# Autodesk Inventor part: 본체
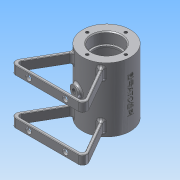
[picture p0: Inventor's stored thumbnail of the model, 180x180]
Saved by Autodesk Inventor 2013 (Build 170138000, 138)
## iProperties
Created: 2016-03
Part Number: 본체
Material: 알루미늄 6061
Document SubType Name: Modeling
Designer: Administrator
Density: 2.71 g/cm^3
Mass: 213.519 g
Surface Area: 333.696 cm^2
Volume: 78.7893 cm^3
Author: Administrator
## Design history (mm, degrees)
sketch "스케치1"
  geometry: C1 r 26 at (0, 0); 1 further point
  constraints: 1 centre point, 1 coincident
  dimensions: "d0" = 52 diameter of C1
extrude "돌출1" new body sketch "스케치1" distance "d1" = 35; taper "d2" = 0 deg
node "작업 평면1"
sketch "스케치2"
  geometry: L1 (0, 0)-(0, -65); L2 (-42.594, -65)-(42.594, -65); L3 (0, 8.775)-(-42.594, -65); L4 (42.594, -65)-(0, 8.775); 2 further points
  constraints: 8 end point, 1 midpoint, 1 perpendicular, 1 point on line, 1 vertical, 2 other
  dimensions: "d4" = 65 distance of L1.end L1.start; "d5" = 30 deg angle of L1 L3; "d7" = 30 deg angle of L4 L1 (derived); "d9" = 85.18802 distance of L2.start L2.end; "d10" = 73.77499 vertical distance of L2.end L3.start; "d97" = 45 distance from line of L2 point (16.613, -20) (derived)
feature "리브1" sketch "스케치2" dims "d11" = 3, "d12" = 10, "d13" = 0, "d14" = 0, "d15" = 1, "d16" = 1
hole "구멍1" diameter "d19" = 28; stored, may be unused: countersink angle "d23" = 90 deg, drill point angle "d25" = 0 deg; dims "d17" = 10, "d18" = 10, "d20" = 6, "d21" = 32, "d22" = 12, "d24" = 14
hole "구멍2" diameter "d28" = 42; stored, may be unused: countersink angle "d32" = 90 deg, drill point angle "d34" = 0 deg; dims "d26" = 10, "d27" = 10, "d29" = 6, "d30" = 32, "d31" = 12, "d33" = 21
sketch "스케치3"
  geometry: C1 r 16 at (0, 0) reference; 1 further point
  constraints: 1 vertical alignment
  dimensions: "d35" = 21 distance of C1.centre point (0, 21)
hole "구멍3" sketch "스케치3" at (0, 21) diameter "d36" = 3.242; stored, may be unused: countersink angle "d40" = 90 deg, drill point angle "d42" = 118 deg; dims "d37" = 8, "d38" = 32, "d39" = 12, "d41" = 10
fillet "모깎기1" dims "d46" = 0.3
fillet "모깎기2" dims "d47" = 3
fillet "모깎기3" dims "d48" = 5
fillet "모깎기4" dims "d49" = 3
fillet "모깎기5" dims "d50" = 0.5
fillet "모깎기6" dims "d51" = 3
node "작업 평면2"
sketch "스케치4"
  geometry: C1 r 5 at (0, 0); 1 further point
  constraints: 1 centre point, 1 coincident
  dimensions: "d53" = 10 diameter of C1
extrude "돌출2" join sketch "스케치4" stored distance "d54" = 35; taper "d55" = 0 deg
hole "구멍4" diameter "d58" = 5.188; stored, may be unused: countersink angle "d62" = 90 deg, drill point angle "d64" = 118 deg; dims "d56" = 10, "d57" = 10, "d59" = 8, "d60" = 32, "d61" = 12, "d63" = 10
sketch "스케치5"
  geometry: L1 (-5, 25.515)-(-5, 29) reference; L2 (-5, 29)-(-2.594, 29) reference; L3 (-2.594, 29)-(-2.594, 20.839) reference; L4 (2.594, 20.839)-(2.594, 29) reference; L5 (2.594, 29)-(5, 29) reference; L6 (5, 29)-(5, 25.515) reference; L7 (0, 0)-(-7.506, -28.012); L8 (0, 0)-(29, 0); A1 r 21 centre (0, 0) between (-2.594, 20.839) and (2.594, 20.839) reference; A2 r 26 centre (0, 0) between (-5, 25.515) and (5, 25.515) reference; 1 further point
  constraints: 4 end point, 1 equal length, 1 horizontal
  dimensions: "d66" = 29 distance of L7.start L7.end; "d67" = 105 deg angle of L7 L8
  node "절단 모서리 투영1"
node "작업 평면3"
sketch "스케치6"
  geometry: C1 r 6 at (0, 0); 1 further point
  constraints: 1 centre point, 1 coincident
  dimensions: "d68" = 12 diameter of C1
extrude "돌출3" join sketch "스케치6" stored distance "d69" = 35; taper "d70" = 0 deg
sketch "스케치7"
  geometry: C1 r 6 at (0, 0) reference; 1 further point
  constraints: 1 coincident
hole "구멍5" sketch "스케치7" at (0, 0) diameter "d71" = 5.188; stored, may be unused: countersink angle "d75" = 90 deg, drill point angle "d77" = 118 deg; dims "d72" = 8, "d73" = 32, "d74" = 12, "d76" = 10
fillet "모깎기8" dims "d78" = 2
node "작업 평면4"
sketch "스케치8"
  geometry: L1 (-65, -29.5)-(-65, -20.5) reference; 2 further points
  constraints: 1 coincident, 1 other
  dimensions: "d79" = 65 distance from line of point (0, 0) L1 (derived)
feature "엠보싱1" sketch "스케치8" dims "d1" = 35, "d30" = 32, "d80" = 0.5, "d81" = 0
sketch "스케치9"
  geometry: L1 (66.206, 50.5)-(70.167, 50.5) reference; L2 (70.718, 50)-(70.718, 41) reference; L3 (70.167, 40.5)-(66.206, 40.5) reference; L4 (64.403, 41)-(64.403, 50) reference; L5 (64.403, 41)-(0, 41) reference; L6 (0, 41)-(0, 50) reference; L7 (0, 50)-(64.403, 50) reference; L8 (-1.803, 40.5)-(-5.763, 40.5) reference; L9 (-6.315, 41)-(-6.315, 50) reference; L10 (-5.763, 50.5)-(-1.803, 50.5) reference; L11 (-1.803, -9.5)-(-5.763, -9.5) reference; L12 (-6.315, -9)-(-6.315, 0) reference; L13 (-5.763, 0.5)-(-1.803, 0.5) reference; L14 (0, 0)-(64.403, 0) reference; L15 (64.403, -9)-(64.403, 0) reference; L16 (70.167, -9.5)-(66.206, -9.5) reference; L17 (70.718, 0)-(70.718, -9) reference; L18 (66.206, 0.5)-(70.167, 0.5) reference; L19 (0, -9)-(0, 0) reference; L20 (64.403, -9)-(0, -9) reference; L21 (0, -9.5)-(64.403, -9.5) reference; 5 further points
  constraints: 2 horizontal alignment, 2 vertical alignment, 16 other
  dimensions: "d82" = 20 horizontal distance of point (32.202, 20.5) point (12.202, 45.5); "d83" = 5 distance from line of L1 point (52.202, 45.5); "d84" = 40 distance of point (52.202, 45.5) point (12.202, 45.5); "d86" = 5 distance from line of point (12.202, -4.5) L21
hole "구멍6" sketch "스케치9" at (12.202, -4.5), (52.202, -4.5), (12.202, 45.5), (52.202, 45.5) diameter "d87" = 6; stored, may be unused: countersink angle "d91" = 90 deg, drill point angle "d93" = 0 deg; dims "d88" = 8, "d89" = 32, "d90" = 12, "d92" = 10
chamfer "모따기1" distance "d94" = 1; stored, may be unused: second distance "d95" = 2, angle "d96" = 45 deg
node "솔리드1"
pattern_circular "원형 패턴1" dims angle "d44" = 360 deg
mirror "대칭1"
node "투영된 루프1"
node "절단 모서리 투영2"
other parameters: "d52" = 29
